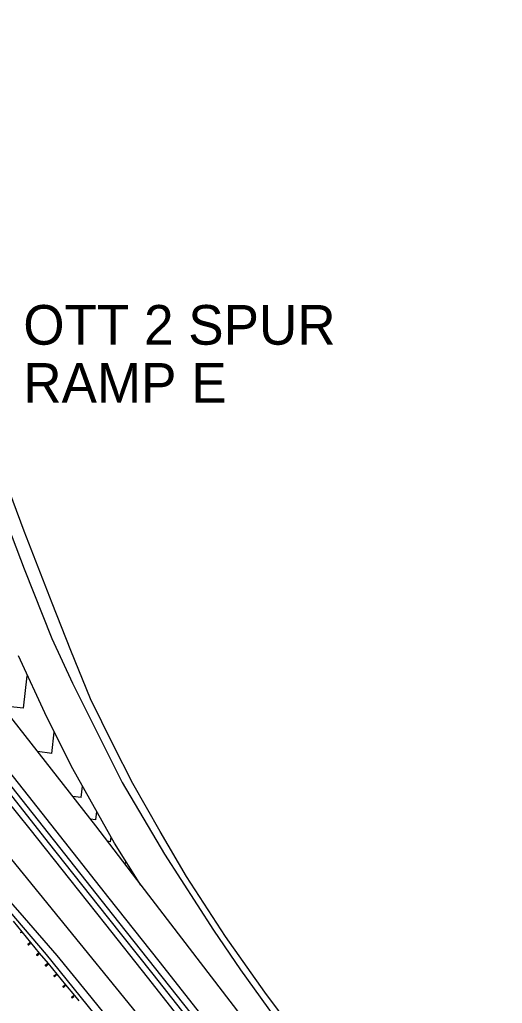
# Model space of a CAD drawing. Extents: x 1855721 to 1876784, y 662259 to 674089.
# Drawn here: x 1856995.6 to 1857214.7, y 673212.8 to 673659.3 of the extents above; entities that cross this region are included whole.
import ezdxf

# ---------------------------------------------------------------- set-up
doc = ezdxf.new("R2010")
doc.units = 0
for name, color, linetype in [('_CIVIL_CONSTRUCTION', 7, 'Continuous'), ('GE_X_Alignment_100_Cardinal_Points', 7, 'Continuous'), ('GE_X_Alignment_100_Curve_Data', 7, 'Continuous'), ('GE_X_Alignment_100_Distances', 7, 'Continuous'), ('GE_X_Alignment_100_Stations', 7, 'Continuous'), ('RD_P_Anchor_Assembly', 7, 'Continuous'), ('SC_Scratch1', 7, 'Continuous')]:
    doc.layers.add(name, color=color, linetype=linetype)

msp = doc.modelspace()

# ---------------------------------------------------------------- linework, layer by layer
at = {"layer": '_CIVIL_CONSTRUCTION'}
for points in [[(1856907.94, 673754.45), (1856898.32, 673746.66), (1856890.16, 673734.18), (1856887.31, 673714.01), (1856892.25, 673692.55), (1856907.26, 673651.21), (1856926.05, 673599.53), (1856939.44, 673563.9), (1856970.18, 673481.83), (1856997.54, 673409.99), (1857010.24, 673378.46), (1857019.53, 673358.08), (1857042.16, 673313.09), (1857061.25, 673280.57), (1857083.54, 673246.08), (1857095.78, 673228.1), (1857114.49, 673202.22)], [(1856617.27, 673552.42), (1856655.88, 673523.89), (1856692.85, 673496.68), (1856732.12, 673468.03), (1856753.04, 673452.75), (1856787.2, 673427.67), (1856817.3, 673405.57), (1856839.3, 673389.32), (1856865.64, 673369.86), (1856887.55, 673353.68), (1856906.71, 673338.47), (1856928.16, 673320.89), (1856947.88, 673303.78), (1856964.66, 673286.98), (1856980.64, 673270.87), (1856997.65, 673251.6), (1857012.47, 673234.52), (1857025.83, 673218.1), (1857043.32, 673196.63)]]:
    msp.add_lwpolyline(points, dxfattribs=at)
at = {"layer": 'GE_X_Alignment_100_Cardinal_Points'}
msp.add_lwpolyline([(1856977.66, 673360.11), (1857030.03, 673293.34), (1857050.52, 673266.41), (1857038.65, 673285.44), (1857019.72, 673319.21), (1857007.87, 673342.67), (1856995.1, 673370.58)], dxfattribs=at)
at = {"layer": 'GE_X_Alignment_100_Curve_Data'}
for points in [[(1857084.52, 673199.44), (1857058.84, 673231.89), (1857036.21, 673260.51), (1857005.72, 673299.13), (1856977.91, 673334.27), (1856956.33, 673361.4), (1856932.27, 673391.54), (1856905.5, 673425.34), (1856874.29, 673464.62), (1856845.61, 673500.69), (1856797.58, 673561.38), (1856776.76, 673587.64), (1856740.03, 673633.92), (1856719.16, 673660.21)], [(1857069.24, 673204.89), (1857053.62, 673224.64), (1857034.69, 673248.57), (1857018.33, 673269.25), (1857000.34, 673291.81), (1856989.13, 673305.85), (1856974.88, 673323.72), (1856961.69, 673340.3), (1856947.89, 673357.65), (1856932.81, 673376.6), (1856919.64, 673393.18), (1856902.6, 673414.7), (1856891.01, 673429.33), (1856876.35, 673447.79), (1856858.48, 673470.29), (1856836.04, 673498.65), (1856817.98, 673521.49), (1856799.13, 673545.33), (1856784.03, 673564.41), (1856768.87, 673583.54), (1856753.84, 673602.5), (1856737.18, 673623.53), (1856724.11, 673640.04), (1856709.64, 673658.36)]]:
    msp.add_lwpolyline(points, dxfattribs=at)
at = {"layer": 'GE_X_Alignment_100_Distances'}
for points in [[(1856952.81, 673325.9), (1857109.21, 673133.75), (1857188.59, 673029.16)], [(1857050.52, 673266.41), (1857141.34, 673148.16), (1857253.23, 673011.76)]]:
    msp.add_lwpolyline(points, dxfattribs=at)
at = {"layer": 'GE_X_Alignment_100_Stations'}
for p, q in [((1856997.31, 673346.72), (1856999.03, 673361.46)), ((1856997.31, 673346.72), (1856987.24, 673347.89)), ((1857010.16, 673326.28), (1857011.29, 673335.9)), ((1857010.16, 673326.28), (1857003.59, 673327.05)), ((1857023.46, 673306.2), (1857024.07, 673311.44)), ((1857023.46, 673306.2), (1857019.59, 673306.66)), ((1857030.11, 673296.16), (1857030.54, 673299.9)), ((1857030.11, 673296.16), (1857027.59, 673296.46)), ((1857036.84, 673286.19), (1857035.34, 673286.36)), ((1857036.84, 673286.19), (1857037.08, 673288.24)), ((1857043.68, 673276.3), (1857042.93, 673276.39)), ((1857043.68, 673276.3), (1857043.79, 673277.21))]:
    msp.add_line(p, q, dxfattribs=at)
at = {"layer": 'RD_P_Anchor_Assembly'}
for p, q in [((1856992.54, 673250.12), (1856996.52, 673245.3)), ((1856996.03, 673244.94), (1856996.13, 673245.02)), ((1856996.03, 673244.94), (1856996.07, 673244.89)), ((1856996.05, 673244.97), (1856996.1, 673244.91)), ((1856996.09, 673245.01), (1856996.06, 673244.98)), ((1856996.09, 673245.05), (1856996.07, 673245.04)), ((1856996.07, 673244.89), (1856996.17, 673244.97)), ((1856996.08, 673245.04), (1856996.17, 673244.92)), ((1856996.09, 673245.04), (1856996.11, 673245.05)), ((1856996.09, 673245.04), (1856996.3, 673244.78)), ((1856996.11, 673245.05), (1856996.21, 673244.93)), ((1856996.16, 673244.94), (1856996.12, 673244.91)), ((1856996.5, 673245.32), (1856996.13, 673245.02)), ((1856996.54, 673245.27), (1856996.17, 673244.97)), ((1856996.19, 673244.92), (1856996.17, 673244.92)), ((1856996.21, 673244.93), (1856996.56, 673245.22)), ((1856996.22, 673244.91), (1856996.57, 673245.21)), ((1856996.22, 673244.91), (1856996.32, 673244.79)), ((1856996.3, 673244.78), (1856996.32, 673244.79)), ((1856996.46, 673245.34), (1856996.47, 673245.35)), ((1856996.46, 673245.34), (1856996.56, 673245.22)), ((1856996.47, 673245.35), (1856996.68, 673245.1)), ((1856996.52, 673245.3), (1857000.5, 673240.48)), ((1856996.57, 673245.21), (1856996.67, 673245.08)), ((1856996.67, 673245.08), (1856996.68, 673245.1)), ((1856999.21, 673239.72), (1856999.98, 673240.35)), ((1856999.27, 673239.63), (1857000.03, 673240.26)), ((1856999.31, 673239.59), (1857000.07, 673240.22)), ((1856999.51, 673239.36), (1857000.27, 673240)), ((1856999.99, 673240.35), (1857000.02, 673240.32)), ((1857000, 673240.3), (1857000.02, 673240.32)), ((1857000, 673240.3), (1857000.23, 673240.02)), ((1857000.03, 673240.3), (1857000.01, 673240.29)), ((1857000.01, 673240.29), (1857000.22, 673240.04)), ((1857000.02, 673240.31), (1857000.03, 673240.32)), ((1857000.13, 673240.34), (1857000.03, 673240.26)), ((1857000.03, 673240.32), (1857000.13, 673240.2)), ((1857000.03, 673240.3), (1857000.13, 673240.18)), ((1857000.05, 673240.3), (1857000.08, 673240.33)), ((1857000.17, 673240.3), (1857000.07, 673240.22)), ((1857000.1, 673240.33), (1857000.15, 673240.27)), ((1857000.11, 673240.23), (1857000.15, 673240.26)), ((1857000.12, 673240.19), (1857000.13, 673240.2)), ((1857000.48, 673240.47), (1857000.13, 673240.18)), ((1857000.49, 673240.46), (1857000.13, 673240.17)), ((1857000.13, 673240.34), (1857000.17, 673240.3)), ((1857000.13, 673240.17), (1857000.23, 673240.05)), ((1857000.23, 673240.05), (1857000.22, 673240.04)), ((1857000.23, 673240.02), (1857000.25, 673240.04)), ((1857000.25, 673240.04), (1857000.27, 673240.01)), ((1857000.39, 673240.6), (1857000.38, 673240.59)), ((1857000.38, 673240.59), (1857000.48, 673240.47)), ((1857000.39, 673240.6), (1857000.6, 673240.35)), ((1857000.49, 673240.46), (1857000.59, 673240.34)), ((1857000.5, 673240.48), (1857004.47, 673235.66)), ((1857000.6, 673240.35), (1857000.59, 673240.34)), ((1856999.21, 673239.7), (1856999.49, 673239.36)), ((1857003.19, 673234.9), (1857003.96, 673235.53)), ((1857003.25, 673234.81), (1857004.01, 673235.44)), ((1857003.29, 673234.77), (1857004.05, 673235.4)), ((1857003.97, 673235.53), (1857004, 673235.5)), ((1857003.98, 673235.48), (1857004, 673235.5)), ((1857003.98, 673235.48), (1857004.21, 673235.2)), ((1857003.99, 673235.49), (1857004.01, 673235.5)), ((1857004, 673235.48), (1857003.99, 673235.47)), ((1857003.99, 673235.47), (1857004.2, 673235.22)), ((1857004, 673235.48), (1857004.1, 673235.36)), ((1857004.11, 673235.52), (1857004.01, 673235.44)), ((1857004.01, 673235.5), (1857004.11, 673235.38)), ((1857004.02, 673235.48), (1857004.06, 673235.51)), ((1857004.15, 673235.48), (1857004.05, 673235.4)), ((1857004.08, 673235.51), (1857004.13, 673235.45)), ((1857004.09, 673235.41), (1857004.13, 673235.44)), ((1857004.09, 673235.37), (1857004.11, 673235.38)), ((1857004.46, 673235.65), (1857004.1, 673235.36)), ((1857004.47, 673235.64), (1857004.11, 673235.35)), ((1857004.11, 673235.52), (1857004.15, 673235.48)), ((1857004.37, 673235.78), (1857004.36, 673235.77)), ((1857004.36, 673235.77), (1857004.46, 673235.65)), ((1857004.37, 673235.78), (1857004.58, 673235.53)), ((1857004.47, 673235.66), (1857008.45, 673230.84)), ((1857004.47, 673235.64), (1857004.57, 673235.52)), ((1857004.58, 673235.53), (1857004.57, 673235.52)), ((1857003.19, 673234.88), (1857003.47, 673234.54)), ((1857003.48, 673234.54), (1857004.25, 673235.18)), ((1857004.11, 673235.35), (1857004.21, 673235.23)), ((1857004.21, 673235.23), (1857004.2, 673235.22)), ((1857004.21, 673235.2), (1857004.23, 673235.22)), ((1857004.23, 673235.22), (1857004.25, 673235.19)), ((1857008.35, 673230.96), (1857008.33, 673230.95)), ((1857008.33, 673230.95), (1857008.43, 673230.83)), ((1857008.35, 673230.96), (1857008.56, 673230.71)), ((1857007.17, 673230.08), (1857007.94, 673230.71)), ((1857007.17, 673230.06), (1857007.45, 673229.72)), ((1857007.23, 673229.99), (1857007.99, 673230.62)), ((1857007.27, 673229.95), (1857008.03, 673230.58)), ((1857007.46, 673229.72), (1857008.23, 673230.36)), ((1857007.95, 673230.71), (1857007.98, 673230.68)), ((1857007.96, 673230.66), (1857007.98, 673230.68)), ((1857007.96, 673230.66), (1857008.19, 673230.38)), ((1857007.97, 673230.67), (1857007.98, 673230.68)), ((1857007.98, 673230.66), (1857007.97, 673230.65)), ((1857007.97, 673230.65), (1857008.18, 673230.4)), ((1857007.98, 673230.68), (1857008.08, 673230.56)), ((1857007.98, 673230.66), (1857008.08, 673230.54)), ((1857008.09, 673230.7), (1857007.99, 673230.62)), ((1857008, 673230.66), (1857008.04, 673230.69)), ((1857008.13, 673230.66), (1857008.03, 673230.58)), ((1857008.06, 673230.69), (1857008.11, 673230.63)), ((1857008.07, 673230.59), (1857008.1, 673230.62)), ((1857008.07, 673230.55), (1857008.08, 673230.56)), ((1857008.43, 673230.83), (1857008.08, 673230.54)), ((1857008.44, 673230.82), (1857008.09, 673230.53)), ((1857008.09, 673230.7), (1857008.13, 673230.66)), ((1857008.09, 673230.53), (1857008.19, 673230.41)), ((1857008.19, 673230.41), (1857008.18, 673230.4)), ((1857008.19, 673230.38), (1857008.21, 673230.4)), ((1857008.21, 673230.4), (1857008.23, 673230.37)), ((1857008.44, 673230.82), (1857008.54, 673230.7)), ((1857008.45, 673230.84), (1857012.43, 673226.02)), ((1857008.56, 673230.71), (1857008.54, 673230.7)), ((1857011.15, 673225.26), (1857011.92, 673225.89)), ((1857011.15, 673225.24), (1857011.43, 673224.9)), ((1857011.2, 673225.17), (1857011.97, 673225.8)), ((1857011.24, 673225.13), (1857012.01, 673225.76)), ((1857011.44, 673224.9), (1857012.21, 673225.54)), ((1857011.93, 673225.89), (1857011.96, 673225.86)), ((1857011.94, 673225.84), (1857011.96, 673225.86)), ((1857011.94, 673225.84), (1857012.17, 673225.56)), ((1857011.95, 673225.85), (1857011.96, 673225.86)), ((1857011.96, 673225.84), (1857011.95, 673225.83)), ((1857011.95, 673225.83), (1857012.16, 673225.58)), ((1857011.96, 673225.86), (1857012.06, 673225.74)), ((1857011.96, 673225.84), (1857012.06, 673225.72)), ((1857012.07, 673225.88), (1857011.97, 673225.8)), ((1857011.98, 673225.84), (1857012.02, 673225.87)), ((1857012.11, 673225.84), (1857012.01, 673225.76)), ((1857012.04, 673225.87), (1857012.09, 673225.81)), ((1857012.04, 673225.77), (1857012.08, 673225.8)), ((1857012.05, 673225.73), (1857012.06, 673225.74)), ((1857012.41, 673226.01), (1857012.06, 673225.72)), ((1857012.42, 673226), (1857012.07, 673225.71)), ((1857012.07, 673225.88), (1857012.11, 673225.84)), ((1857012.07, 673225.71), (1857012.17, 673225.59)), ((1857012.17, 673225.59), (1857012.16, 673225.58)), ((1857012.17, 673225.56), (1857012.19, 673225.58)), ((1857012.19, 673225.58), (1857012.21, 673225.55)), ((1857012.33, 673226.14), (1857012.31, 673226.13)), ((1857012.31, 673226.13), (1857012.41, 673226.01)), ((1857012.33, 673226.14), (1857012.54, 673225.89)), ((1857012.42, 673226), (1857012.52, 673225.88)), ((1857012.43, 673226.02), (1857016.41, 673221.2)), ((1857012.54, 673225.89), (1857012.52, 673225.88)), ((1857015.13, 673220.44), (1857015.9, 673221.07)), ((1857015.13, 673220.42), (1857015.41, 673220.08)), ((1857015.18, 673220.35), (1857015.95, 673220.98)), ((1857015.22, 673220.31), (1857015.99, 673220.94)), ((1857015.42, 673220.08), (1857016.19, 673220.72)), ((1857015.91, 673221.07), (1857015.93, 673221.04)), ((1857015.92, 673221.02), (1857015.93, 673221.04)), ((1857015.92, 673221.02), (1857016.15, 673220.74)), ((1857015.93, 673221.03), (1857015.94, 673221.04)), ((1857015.94, 673221.02), (1857015.93, 673221.01)), ((1857015.93, 673221.01), (1857016.14, 673220.76)), ((1857015.94, 673221.04), (1857016.04, 673220.92)), ((1857015.94, 673221.02), (1857016.04, 673220.9)), ((1857016.04, 673221.06), (1857015.95, 673220.98)), ((1857015.96, 673221.02), (1857016, 673221.05)), ((1857016.08, 673221.02), (1857015.99, 673220.94)), ((1857016.02, 673221.05), (1857016.07, 673220.99)), ((1857016.02, 673220.95), (1857016.06, 673220.98)), ((1857016.03, 673220.91), (1857016.04, 673220.92)), ((1857016.39, 673221.19), (1857016.04, 673220.9)), ((1857016.04, 673221.06), (1857016.08, 673221.02)), ((1857016.4, 673221.18), (1857016.05, 673220.89)), ((1857016.05, 673220.89), (1857016.15, 673220.77)), ((1857016.15, 673220.77), (1857016.14, 673220.76)), ((1857016.15, 673220.74), (1857016.16, 673220.76)), ((1857016.16, 673220.76), (1857016.19, 673220.73)), ((1857016.31, 673221.32), (1857016.29, 673221.31)), ((1857016.29, 673221.31), (1857016.39, 673221.19)), ((1857016.31, 673221.32), (1857016.52, 673221.07)), ((1857016.4, 673221.18), (1857016.5, 673221.06)), ((1857016.41, 673221.2), (1857020.39, 673216.38)), ((1857016.52, 673221.07), (1857016.5, 673221.06)), ((1857019.11, 673215.62), (1857019.87, 673216.25)), ((1857019.11, 673215.6), (1857019.38, 673215.26)), ((1857019.16, 673215.53), (1857019.93, 673216.16)), ((1857019.2, 673215.49), (1857019.97, 673216.12)), ((1857019.4, 673215.26), (1857020.17, 673215.9)), ((1857019.89, 673216.25), (1857019.91, 673216.22)), ((1857019.89, 673216.2), (1857019.91, 673216.22)), ((1857019.89, 673216.2), (1857020.12, 673215.92)), ((1857019.92, 673216.2), (1857019.9, 673216.19)), ((1857019.9, 673216.19), (1857020.11, 673215.94)), ((1857019.91, 673216.21), (1857019.92, 673216.22)), ((1857019.92, 673216.22), (1857020.02, 673216.1)), ((1857019.92, 673216.2), (1857020.02, 673216.08)), ((1857020.02, 673216.24), (1857019.93, 673216.16)), ((1857019.94, 673216.2), (1857019.98, 673216.23)), ((1857020.06, 673216.2), (1857019.97, 673216.12)), ((1857019.99, 673216.23), (1857020.04, 673216.17)), ((1857020, 673216.13), (1857020.04, 673216.16)), ((1857020.01, 673216.09), (1857020.02, 673216.1)), ((1857020.37, 673216.37), (1857020.02, 673216.08)), ((1857020.02, 673216.24), (1857020.06, 673216.2)), ((1857020.38, 673216.36), (1857020.03, 673216.07)), ((1857020.03, 673216.07), (1857020.13, 673215.95)), ((1857020.13, 673215.95), (1857020.11, 673215.94)), ((1857020.12, 673215.92), (1857020.14, 673215.94)), ((1857020.14, 673215.94), (1857020.17, 673215.91)), ((1857020.28, 673216.5), (1857020.27, 673216.49)), ((1857020.27, 673216.49), (1857020.37, 673216.37)), ((1857020.28, 673216.5), (1857020.49, 673216.25)), ((1857020.38, 673216.36), (1857020.48, 673216.24)), ((1857020.39, 673216.38), (1857022.38, 673213.97)), ((1857020.49, 673216.25), (1857020.48, 673216.24))]:
    msp.add_line(p, q, dxfattribs=at)
for centre, start, end in [((1856999.99, 673240.34), 39.5384, 129.5384), ((1857000.27, 673240), 309.5384, 39.5384), ((1856999.22, 673239.71), 129.5384, 219.5384), ((1856999.5, 673239.37), 219.5384, 309.5384), ((1857003.97, 673235.52), 39.5384, 129.5384), ((1857003.2, 673234.89), 129.5384, 219.5384), ((1857003.48, 673234.55), 219.5384, 309.5384), ((1857004.24, 673235.18), 309.5384, 39.5384), ((1857007.18, 673230.07), 129.5384, 219.5384), ((1857007.46, 673229.73), 219.5384, 309.5384), ((1857007.94, 673230.7), 39.5384, 129.5384), ((1857008.22, 673230.36), 309.5384, 39.5384), ((1857011.16, 673225.25), 129.5384, 219.5384), ((1857011.44, 673224.91), 219.5384, 309.5384), ((1857011.92, 673225.88), 39.5384, 129.5384), ((1857012.2, 673225.54), 309.5384, 39.5384), ((1857015.13, 673220.43), 129.5384, 219.5384), ((1857015.41, 673220.09), 219.5384, 309.5384), ((1857015.9, 673221.06), 39.5384, 129.5384), ((1857016.18, 673220.72), 309.5384, 39.5384), ((1857019.11, 673215.61), 129.5384, 219.5384), ((1857019.39, 673215.27), 219.5384, 309.5384), ((1857019.88, 673216.24), 39.5384, 129.5384), ((1857020.16, 673215.9), 309.5384, 39.5384)]:
    msp.add_arc(centre, 0.01, start, end, dxfattribs=at)
for centre, major_axis, ratio, start_param, end_param in [((1856996.06, 673244.97), (0.0107, 0.0089), 0.929688, 1.560203, 2.937581), ((1856996.11, 673244.92), (0.0108, 0.0089), 0.929688, 3.385779, 4.696983), ((1856996.52, 673245.3), (0.0664, -0.0805), 0.312583, 6.203436, 9.504527), ((1857000.09, 673240.32), (-0.0107, -0.0089), 0.929688, 3.345604, 4.722982), ((1857000.14, 673240.27), (-0.0108, -0.0089), 0.929688, 1.586202, 2.897406), ((1856999.29, 673239.61), (0.0664, -0.0805), 0.312583, 3.061844, 6.362934), ((1857004.07, 673235.5), (-0.0107, -0.0089), 0.929688, 3.345604, 4.722982), ((1857004.12, 673235.45), (-0.0108, -0.0089), 0.929688, 1.586202, 2.897406), ((1857003.26, 673234.79), (0.0664, -0.0805), 0.312583, 3.061844, 6.362934), ((1857007.24, 673229.97), (0.0664, -0.0805), 0.312583, 3.061844, 6.362934), ((1857008.05, 673230.68), (-0.0107, -0.0089), 0.929688, 3.345604, 4.722982), ((1857008.1, 673230.63), (-0.0108, -0.0089), 0.929688, 1.586202, 2.897406), ((1857011.22, 673225.15), (0.0664, -0.0805), 0.312583, 3.061844, 6.362934), ((1857012.03, 673225.86), (-0.0107, -0.0089), 0.929688, 3.345604, 4.722982), ((1857012.07, 673225.81), (-0.0108, -0.0089), 0.929688, 1.586202, 2.897406), ((1857015.2, 673220.33), (0.0664, -0.0805), 0.312583, 3.061844, 6.362934), ((1857016.01, 673221.04), (-0.0107, -0.0089), 0.929688, 3.345604, 4.722982), ((1857016.05, 673220.99), (-0.0108, -0.0089), 0.929688, 1.586202, 2.897406), ((1857019.18, 673215.51), (0.0664, -0.0805), 0.312583, 3.061844, 6.362934), ((1857019.99, 673216.22), (-0.0107, -0.0089), 0.929688, 3.345604, 4.722982), ((1857020.03, 673216.17), (-0.0108, -0.0089), 0.929688, 1.586202, 2.897406)]:
    msp.add_ellipse(centre, major_axis=major_axis, ratio=ratio, start_param=start_param, end_param=end_param, dxfattribs=at)
at = {"layer": 'SC_Scratch1'}
for points in [[(1857125.9, 673192.38), (1857106.85, 673217.86), (1857089.03, 673243.2), (1857071.28, 673270.35), (1857059.35, 673290.79), (1857046.95, 673312.63), (1857038.08, 673330.2), (1857027.78, 673351.06), (1857018.79, 673372.97), (1857010.27, 673394.49), (1856997.68, 673427.1), (1856985.51, 673459.37), (1856969.73, 673501.38), (1856952.87, 673546.06), (1856924.71, 673620.84), (1856906.01, 673671.37), (1856897.33, 673694.81), (1856892.8, 673715.23), (1856894.39, 673726.2), (1856895.28, 673731.39), (1856902.96, 673743.51), (1856914.8, 673753.61), (1856922.95, 673758.75)], [(1857506.27, 672661.92), (1857419.93, 672771.16), (1857315.59, 672902.87), (1857226.39, 673015.29), (1857156.27, 673103.7), (1857102.52, 673171.6), (1857037.75, 673253.29), (1856965.28, 673344.85), (1856882.51, 673448.91), (1856802.82, 673549.45), (1856753.58, 673611.84), (1856715.89, 673659.59)], [(1856411.13, 673658.05), (1856411.05, 673653.32), (1856433.04, 673650.37), (1856462.45, 673642.46), (1856473.31, 673638.17), (1856489.3, 673631.84), (1856509.35, 673622.69), (1856540.28, 673601.72), (1856602.02, 673557.17), (1856613.52, 673548.81), (1856664.5, 673511.42), (1856681.81, 673498.79), (1856741.91, 673455.6), (1856751.56, 673448.7), (1856803.56, 673411.72), (1856816.22, 673402.71), (1856885.67, 673351.97), (1856905.29, 673336.59), (1856935.26, 673310.9), (1856947.17, 673300.31), (1856979.11, 673268.21), (1856993.62, 673251.34), (1857007.64, 673235.03), (1857042, 673192.53)], [(1856712.69, 673658.93), (1856740.72, 673623.65), (1856759.09, 673600.43), (1856797.94, 673551.31), (1856903.56, 673418.23), (1856938.71, 673373.91), (1856970.61, 673333.81), (1857008.56, 673285.85), (1857035.35, 673252.02), (1857055.95, 673226.05), (1857079.8, 673196), (1857110.23, 673157.64), (1857164.72, 673088.94), (1857203.73, 673039.74), (1857244.27, 672988.5), (1857277.96, 672946.15), (1857290.57, 672930.23), (1857322.95, 672889.42), (1857361.11, 672841.48), (1857423.44, 672762.67), (1857504.02, 672661.22)]]:
    msp.add_lwpolyline(points, dxfattribs=at)

# ---------------------------------------------------------------- texts
for s, p in [('OTT 2 SPUR', (1856997.21, 673511.75)), ('RAMP E', (1856997.21, 673485.41))]:
    msp.add_text(s, height=18, dxfattribs=at).set_placement(p)

doc.saveas('drawing.dxf')
